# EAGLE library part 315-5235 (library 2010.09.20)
Sega 315-5235 Paging Chip Currently, it is believed that the 315-5235 paging chip can handle up to 32 &times; 16KByte memory pages, making it suitable for use with 1, 2, and 4 Megabit games. Additionally, this chip is believed to contain the logic necessary for handling battery-backup RAM. The fact that this chip is known to appear in a Phantasy Star (4 Megabit Plus) supports these two beliefs. Information in this document is compiled from postings by Mike G. and Charles Mac Donald on the S8-Dev Forum, and from personal investigations by Zoop and Eric Quinn. Drawn by Darren Lue Choy 2010.09.20
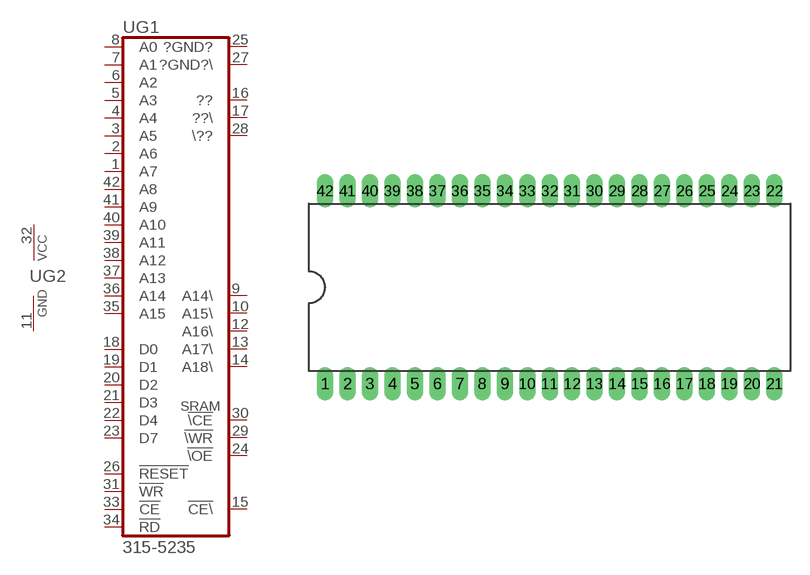
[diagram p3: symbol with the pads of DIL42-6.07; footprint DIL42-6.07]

Designator prefix -; gates G1=315-5235 G2=PWRN

## 315-5235  [DIL42-6.07]
1  G1:A7  in
2  G1:A6  in
3  G1:A5  in
4  G1:A4  in
5  G1:A3  in
6  G1:A2  in
7  G1:A1  in
8  G1:A0  in
9  G1:A14\  out
10  G1:A15\  out
11  G2:GND  pwr
12  G1:A16\  out
13  G1:A17\  out
14  G1:A18\  out
15  G1:!CE\  out
16  G1:??
17  G1:??\
18  G1:D0  in
19  G1:D1  in
20  G1:D2  in
21  G1:D3  in
22  G1:D4  in
23  G1:D7  in
24  G1:!\OE  out
25  G1:?GND?  in
26  G1:!RESET  in
27  G1:?GND?\  in
28  G1:\??
29  G1:!\WR  out
30  G1:!\CE  out
31  G1:!WR  in
32  G2:VCC  pwr
33  G1:!CE  in
34  G1:!RD  in
35  G1:A15  in
36  G1:A14  in
37  G1:A13  in
38  G1:A12  in
39  G1:A11  in
40  G1:A10  in
41  G1:A9  in
42  G1:A8  in

## Footprint DIL42-6.07 (pad centres in mm)
Dual In Line Package 0.6 inch 0.07 pitch Drawn by D Lue Choy &micro; 2010.09.20
drill 0.813 long: 1 -17.78,-7.62; 2 -16.002,-7.62; 3 -14.224,-7.62; 4 -12.446,-7.62; 5 -10.668,-7.62; 6 -8.89,-7.62; 7 -7.112,-7.62; 8 -5.334,-7.62; 9 -3.556,-7.62; 10 -1.778,-7.62; 11 0,-7.62; 12 1.778,-7.62; 13 3.556,-7.62; 14 5.334,-7.62; 15 7.112,-7.62; 16 8.89,-7.62; 17 10.668,-7.62; 18 12.446,-7.62; 19 14.224,-7.62; 20 16.002,-7.62; 21 17.78,-7.62; 22 17.78,7.62; 23 16.002,7.62; 24 14.224,7.62; 25 12.446,7.62; 26 10.668,7.62; 27 8.89,7.62; 28 7.112,7.62; 29 5.334,7.62; 30 3.556,7.62; 31 1.778,7.62; 32 0,7.62; 33 -1.778,7.62; 34 -3.556,7.62; 35 -5.334,7.62; 36 -7.112,7.62; 37 -8.89,7.62; 38 -10.668,7.62; 39 -12.446,7.62; 40 -14.224,7.62; 41 -16.002,7.62; 42 -17.78,7.62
